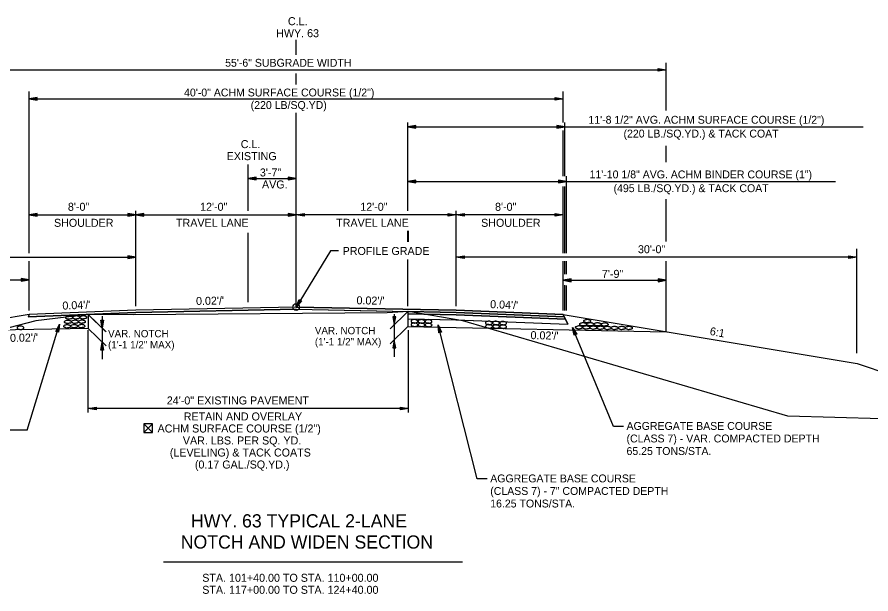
# Model space of a CAD drawing. Extents: x 1461846 to 1462006, y 1686171 to 1686805.
# Drawn here: x 1461905.3 to 1461969.2, y 1686761.5 to 1686804.7 of the extents above; entities that cross this region are included whole.
import ezdxf

# ---------------------------------------------------------------- set-up
doc = ezdxf.new("R2010")
doc.units = 0
for name, color, linetype in [('1', 7, 'Continuous'), ('10', 7, 'Continuous'), ('12', 7, 'Continuous'), ('19', 7, 'Continuous'), ('20', 7, 'Continuous'), ('3', 7, 'Continuous'), ('42', 7, 'Continuous'), ('R_Draft', 7, 'Continuous')]:
    doc.layers.add(name, color=color, linetype=linetype)

# ---------------------------------------------------------------- blocks, each defined once
blk = doc.blocks.new('ROCKS')
at = {"layer": '1'}
blk.add_spline([(0.013, 0.06), (0.053, 0.053), (0.107, 0.033), (0.133, 0.013), (0.133, -0.007), (0.12, -0.033), (0.107, -0.04), (0.073, -0.053), (0.033, -0.067), (0.013, -0.067), (-0.02, -0.06), (-0.06, -0.053), (-0.087, -0.047), (-0.113, -0.02), (-0.113, -0.007), (-0.107, 0.02), (-0.087, 0.033), (-0.067, 0.047), (-0.033, 0.053), (-0.02, 0.06), (0.013, 0.06)], degree=3, dxfattribs=at)

msp = doc.modelspace()

# ---------------------------------------------------------------- linework, layer by layer
at = {"layer": '10'}
for p, q in [((1461915.407, 1686774.246), (1461914.766, 1686773.605)), ((1461914.766, 1686774.246), (1461915.407, 1686773.605))]:
    msp.add_line(p, q, dxfattribs=at)
msp.add_lwpolyline([(1461915.158, 1686773.605), (1461915.407, 1686773.605), (1461915.407, 1686774.246), (1461914.766, 1686774.246), (1461914.766, 1686773.605), (1461915.147, 1686773.605)], dxfattribs=at)
at = {"layer": '19'}
for p, q in [((1461953.889, 1686797.714), (1461953.889, 1686801.288)), ((1461898.458, 1686800.767), (1461953.889, 1686800.767)), ((1461953.289, 1686800.662), (1461953.289, 1686800.872)), ((1461953.289, 1686800.872), (1461953.889, 1686800.767)), ((1461953.289, 1686800.817), (1461953.729, 1686800.782)), ((1461953.889, 1686800.767), (1461953.289, 1686800.662)), ((1461953.729, 1686800.752), (1461953.289, 1686800.712)), ((1461906.174, 1686790.205), (1461906.174, 1686799.138)), ((1461946.174, 1686797.714), (1461946.174, 1686799.138)), ((1461906.774, 1686798.7), (1461906.174, 1686798.595)), ((1461906.174, 1686798.595), (1461946.174, 1686798.595)), ((1461906.174, 1686798.595), (1461906.774, 1686798.49)), ((1461906.774, 1686798.645), (1461906.334, 1686798.61)), ((1461906.334, 1686798.58), (1461906.774, 1686798.54)), ((1461906.774, 1686798.49), (1461906.774, 1686798.7)), ((1461945.574, 1686798.49), (1461945.574, 1686798.7)), ((1461945.574, 1686798.7), (1461946.174, 1686798.595)), ((1461945.574, 1686798.645), (1461946.014, 1686798.61)), ((1461946.174, 1686798.595), (1461945.574, 1686798.49)), ((1461946.014, 1686798.58), (1461945.574, 1686798.54)), ((1461926.174, 1686782.995), (1461926.175, 1686797.55)), ((1461946.174, 1686796.817), (1461946.174, 1686797.714)), ((1461946.174, 1686792.8), (1461946.174, 1686796.222)), ((1461953.889, 1686793.84), (1461953.889, 1686795.083)), ((1461922.591, 1686790.2), (1461922.591, 1686793.681)), ((1461946.174, 1686791.088), (1461946.174, 1686792.022)), ((1461946.174, 1686787.026), (1461946.174, 1686791.088)), ((1461953.889, 1686787.911), (1461953.889, 1686791.088)), ((1461922.591, 1686783.353), (1461922.591, 1686788.545)), ((1461884.174, 1686786.726), (1461914.174, 1686786.726)), ((1461913.574, 1686786.832), (1461913.574, 1686786.622)), ((1461914.174, 1686786.726), (1461913.574, 1686786.832)), ((1461914.014, 1686786.741), (1461913.574, 1686786.777)), ((1461913.574, 1686786.622), (1461914.174, 1686786.726)), ((1461913.574, 1686786.672), (1461914.014, 1686786.711)), ((1461938.174, 1686786.726), (1461938.774, 1686786.832)), ((1461968.174, 1686786.726), (1461938.174, 1686786.726)), ((1461938.774, 1686786.622), (1461938.174, 1686786.726)), ((1461938.334, 1686786.741), (1461938.774, 1686786.777)), ((1461938.774, 1686786.672), (1461938.334, 1686786.711)), ((1461938.774, 1686786.832), (1461938.774, 1686786.622)), ((1461953.889, 1686781.149), (1461953.889, 1686786.44)), ((1461967.574, 1686786.621), (1461967.574, 1686786.831)), ((1461967.574, 1686786.831), (1461968.174, 1686786.726)), ((1461967.574, 1686786.776), (1461968.014, 1686786.741)), ((1461968.174, 1686786.726), (1461967.574, 1686786.621)), ((1461968.014, 1686786.711), (1461967.574, 1686786.671)), ((1461926.174, 1686782.995), (1461926.398, 1686783.562)), ((1461926.575, 1686783.452), (1461926.174, 1686782.995)), ((1461926.248, 1686783.136), (1461926.441, 1686783.53)), ((1461926.535, 1686783.474), (1461926.271, 1686783.125)), ((1461926.398, 1686783.562), (1461926.575, 1686783.452)), ((1461906.174, 1686782.435), (1461884.174, 1686778.769)), ((1461914.174, 1686782.589), (1461906.089, 1686782.265)), ((1461906.174, 1686782.435), (1461906.089, 1686782.265)), ((1461914.174, 1686782.755), (1461906.174, 1686782.435)), ((1461910.591, 1686782.445), (1461910.591, 1686781.392)), ((1461926.174, 1686782.995), (1461914.174, 1686782.755)), ((1461926.174, 1686782.829), (1461914.174, 1686782.589)), ((1461926.174, 1686782.995), (1461938.168, 1686782.755)), ((1461926.174, 1686782.829), (1461938.174, 1686782.589)), ((1461934.549, 1686782.66), (1461934.549, 1686781.535)), ((1461934.549, 1686782.494), (1461934.549, 1686782.119)), ((1461934.549, 1686782.494), (1461938.17, 1686782.422)), ((1461934.591, 1686782.494), (1461938.174, 1686782.422)), ((1461938.17, 1686782.755), (1461946.174, 1686782.435)), ((1461938.17, 1686782.589), (1461946.259, 1686782.265)), ((1461938.17, 1686782.422), (1461946.344, 1686782.095)), ((1461946.174, 1686782.435), (1461946.536, 1686781.712)), ((1461946.174, 1686782.435), (1461968.195, 1686778.765)), ((1461911.531, 1686782.022), (1461911.741, 1686782.022)), ((1461911.636, 1686781.422), (1461911.531, 1686782.022)), ((1461911.621, 1686781.582), (1461911.581, 1686782.022)), ((1461911.741, 1686782.022), (1461911.636, 1686781.422)), ((1461911.686, 1686782.022), (1461911.651, 1686781.582)), ((1461933.631, 1686782.259), (1461933.421, 1686782.259)), ((1461933.421, 1686782.259), (1461933.526, 1686781.659)), ((1461933.476, 1686782.259), (1461933.511, 1686781.819)), ((1461933.526, 1686781.659), (1461933.631, 1686782.259)), ((1461933.541, 1686781.819), (1461933.581, 1686782.259)), ((1461934.549, 1686782.119), (1461938.17, 1686782.047)), ((1461934.591, 1686782.119), (1461938.174, 1686782.047)), ((1461938.17, 1686782.047), (1461946.536, 1686781.712)), ((1461946.536, 1686781.712), (1461946.344, 1686782.095)), ((1461946.344, 1686782.095), (1461946.344, 1686782.095)), ((1461910.591, 1686781.392), (1461898.458, 1686781.149)), ((1461906.015, 1686773.763), (1461908.439, 1686781.715)), ((1461908.164, 1686781.173), (1461908.439, 1686781.715)), ((1461908.364, 1686781.111), (1461908.164, 1686781.173)), ((1461908.212, 1686781.159), (1461908.377, 1686781.567)), ((1461908.404, 1686781.559), (1461908.314, 1686781.129)), ((1461908.439, 1686781.715), (1461908.364, 1686781.111)), ((1461934.549, 1686781.536), (1461953.889, 1686781.149)), ((1461939.74, 1686770.123), (1461936.815, 1686781.67)), ((1461936.864, 1686781.064), (1461936.815, 1686781.67)), ((1461936.815, 1686781.67), (1461937.067, 1686781.115)), ((1461936.912, 1686781.077), (1461936.839, 1686781.511)), ((1461936.867, 1686781.519), (1461937.015, 1686781.105)), ((1461946.536, 1686781.712), (1461946.536, 1686781.712)), ((1461949.951, 1686774.056), (1461946.883, 1686781.471)), ((1461947.016, 1686780.878), (1461946.883, 1686781.471)), ((1461946.883, 1686781.471), (1461947.209, 1686780.956)), ((1461947.061, 1686780.897), (1461946.929, 1686781.317)), ((1461946.955, 1686781.328), (1461947.159, 1686780.939)), ((1461933.526, 1686780.534), (1461933.421, 1686779.934)), ((1461933.631, 1686779.934), (1461933.526, 1686780.534)), ((1461937.067, 1686781.115), (1461936.864, 1686781.064)), ((1461947.209, 1686780.956), (1461947.016, 1686780.878)), ((1461911.531, 1686779.769), (1461911.636, 1686780.369)), ((1461911.586, 1686779.769), (1461911.621, 1686780.209)), ((1461911.636, 1686780.369), (1461911.741, 1686779.769)), ((1461911.651, 1686780.209), (1461911.691, 1686779.769)), ((1461933.421, 1686779.934), (1461933.631, 1686779.934)), ((1461933.511, 1686780.374), (1461933.471, 1686779.934)), ((1461933.576, 1686779.934), (1461933.541, 1686780.374)), ((1461911.741, 1686779.769), (1461911.531, 1686779.769)), ((1461968.195, 1686778.765), (1461981.629, 1686774.287)), ((1461906.015, 1686773.763), (1461901.805, 1686773.763)), ((1461950.688, 1686774.056), (1461949.951, 1686774.056)), ((1461940.477, 1686770.123), (1461939.74, 1686770.123))]:
    msp.add_line(p, q, dxfattribs=at)
for points in [[(1461929.357, 1686787.194), (1461928.757, 1686787.194), (1461926.174, 1686782.995)], [(1461946.344, 1686782.095), (1461938.174, 1686782.422), (1461934.549, 1686782.494), (1461934.549, 1686782.494), (1461934.549, 1686782.494)], [(1461934.549, 1686782.119), (1461934.549, 1686782.119), (1461934.549, 1686782.119), (1461938.148, 1686782.047), (1461946.536, 1686781.712)], [(1461994.384, 1686773.924), (1461984.134, 1686774.215), (1461963.023, 1686774.822)]]:
    msp.add_lwpolyline(points, dxfattribs=at)
for points in [[(1461906.089, 1686782.265), (1461914.174, 1686782.589), (1461926.174, 1686782.829), (1461938.259, 1686782.585), (1461946.259, 1686782.265), (1461946.174, 1686782.435), (1461938.168, 1686782.755), (1461926.174, 1686782.995), (1461914.174, 1686782.755), (1461906.174, 1686782.435)], [(1461934.549, 1686782.494), (1461934.549, 1686782.494), (1461934.549, 1686782.494), (1461938.174, 1686782.422), (1461946.344, 1686782.095), (1461946.344, 1686782.095), (1461946.259, 1686782.265), (1461938.17, 1686782.589), (1461934.549, 1686782.66), (1461934.549, 1686782.66), (1461934.549, 1686782.66), (1461934.549, 1686782.66)]]:
    msp.add_lwpolyline(points, close=True, dxfattribs=at)
msp.add_circle((1461926.179, 1686782.993), 0.25, dxfattribs=at)
at = {"layer": '20'}
for p, q in [((1461934.549, 1686790.205), (1461934.549, 1686796.817)), ((1461935.149, 1686796.603), (1461934.549, 1686796.498)), ((1461934.549, 1686796.498), (1461935.149, 1686796.393)), ((1461934.549, 1686796.498), (1461946.299, 1686796.498)), ((1461935.149, 1686796.548), (1461934.709, 1686796.513)), ((1461935.149, 1686796.393), (1461935.149, 1686796.603)), ((1461945.699, 1686796.603), (1461945.699, 1686796.393)), ((1461946.299, 1686796.498), (1461945.699, 1686796.603)), ((1461946.139, 1686796.513), (1461945.699, 1686796.548)), ((1461945.699, 1686796.393), (1461946.299, 1686796.498)), ((1461946.299, 1686792.8), (1461946.299, 1686796.817)), ((1461946.299, 1686796.498), (1461968.649, 1686796.498)), ((1461934.709, 1686796.483), (1461935.149, 1686796.443)), ((1461945.699, 1686796.443), (1461946.139, 1686796.483)), ((1461923.191, 1686792.727), (1461922.591, 1686792.622)), ((1461923.191, 1686792.672), (1461922.751, 1686792.637)), ((1461923.191, 1686792.517), (1461923.191, 1686792.727)), ((1461925.574, 1686792.727), (1461925.574, 1686792.517)), ((1461926.174, 1686792.622), (1461925.574, 1686792.727)), ((1461926.014, 1686792.637), (1461925.574, 1686792.672)), ((1461946.435, 1686787.026), (1461946.435, 1686792.8)), ((1461922.591, 1686792.622), (1461926.174, 1686792.622)), ((1461922.591, 1686792.622), (1461923.191, 1686792.517)), ((1461922.751, 1686792.607), (1461923.191, 1686792.567)), ((1461925.574, 1686792.517), (1461926.174, 1686792.622)), ((1461925.574, 1686792.567), (1461926.014, 1686792.607)), ((1461935.149, 1686792.51), (1461934.549, 1686792.405)), ((1461934.549, 1686792.405), (1461946.435, 1686792.405)), ((1461934.549, 1686792.405), (1461935.149, 1686792.3)), ((1461935.149, 1686792.455), (1461934.709, 1686792.42)), ((1461934.709, 1686792.39), (1461935.149, 1686792.35)), ((1461935.149, 1686792.3), (1461935.149, 1686792.51)), ((1461945.835, 1686792.51), (1461945.835, 1686792.3)), ((1461946.435, 1686792.405), (1461945.835, 1686792.51)), ((1461946.275, 1686792.42), (1461945.835, 1686792.455)), ((1461945.835, 1686792.3), (1461946.435, 1686792.405)), ((1461945.835, 1686792.35), (1461946.275, 1686792.39)), ((1461946.299, 1686787.026), (1461946.299, 1686792.022)), ((1461946.435, 1686792.405), (1461957.904, 1686792.405)), ((1461957.904, 1686792.405), (1461966.582, 1686792.405)), ((1461906.174, 1686787.026), (1461906.174, 1686790.205)), ((1461914.174, 1686783.055), (1461914.174, 1686790.205)), ((1461938.174, 1686783.055), (1461938.174, 1686790.205)), ((1461946.174, 1686787.026), (1461946.174, 1686790.205)), ((1461906.774, 1686790.01), (1461906.174, 1686789.905)), ((1461906.174, 1686789.905), (1461914.174, 1686789.905)), ((1461906.174, 1686789.905), (1461906.774, 1686789.8)), ((1461906.774, 1686789.955), (1461906.334, 1686789.92)), ((1461906.334, 1686789.89), (1461906.774, 1686789.85)), ((1461906.774, 1686789.8), (1461906.774, 1686790.01)), ((1461913.574, 1686790.01), (1461913.574, 1686789.8)), ((1461914.174, 1686789.905), (1461913.574, 1686790.01)), ((1461914.014, 1686789.92), (1461913.574, 1686789.955)), ((1461913.574, 1686789.8), (1461914.174, 1686789.905)), ((1461913.574, 1686789.85), (1461914.014, 1686789.89)), ((1461914.774, 1686790.01), (1461914.174, 1686789.905)), ((1461914.174, 1686789.905), (1461926.174, 1686789.905)), ((1461914.174, 1686789.905), (1461914.774, 1686789.8)), ((1461914.774, 1686789.955), (1461914.334, 1686789.92)), ((1461914.334, 1686789.89), (1461914.774, 1686789.85)), ((1461914.774, 1686789.8), (1461914.774, 1686790.01)), ((1461925.574, 1686790.01), (1461925.574, 1686789.8)), ((1461926.174, 1686789.905), (1461925.574, 1686790.01)), ((1461926.014, 1686789.92), (1461925.574, 1686789.955)), ((1461925.574, 1686789.8), (1461926.174, 1686789.905)), ((1461925.574, 1686789.85), (1461926.014, 1686789.89)), ((1461926.174, 1686789.905), (1461926.774, 1686790.01)), ((1461938.174, 1686789.905), (1461926.174, 1686789.905)), ((1461926.774, 1686789.8), (1461926.174, 1686789.905)), ((1461926.334, 1686789.92), (1461926.774, 1686789.955)), ((1461926.774, 1686789.85), (1461926.334, 1686789.89)), ((1461926.774, 1686790.01), (1461926.774, 1686789.8)), ((1461937.574, 1686789.8), (1461937.574, 1686790.01)), ((1461937.574, 1686790.01), (1461938.174, 1686789.905)), ((1461937.574, 1686789.955), (1461938.014, 1686789.92)), ((1461938.174, 1686789.905), (1461937.574, 1686789.8)), ((1461938.014, 1686789.89), (1461937.574, 1686789.85)), ((1461938.174, 1686789.905), (1461938.774, 1686790.01)), ((1461946.174, 1686789.905), (1461938.174, 1686789.905)), ((1461938.774, 1686789.8), (1461938.174, 1686789.905)), ((1461938.334, 1686789.92), (1461938.774, 1686789.955)), ((1461938.774, 1686789.85), (1461938.334, 1686789.89)), ((1461938.774, 1686790.01), (1461938.774, 1686789.8)), ((1461945.574, 1686789.8), (1461945.574, 1686790.01)), ((1461945.574, 1686790.01), (1461946.174, 1686789.905)), ((1461945.574, 1686789.955), (1461946.014, 1686789.92)), ((1461946.174, 1686789.905), (1461945.574, 1686789.8)), ((1461946.014, 1686789.89), (1461945.574, 1686789.85)), ((1461934.549, 1686787.885), (1461934.549, 1686788.692)), ((1461934.591, 1686787.885), (1461934.591, 1686788.692)), ((1461968.174, 1686779.551), (1461968.174, 1686787.36)), ((1461906.174, 1686782.735), (1461906.174, 1686786.426)), ((1461934.549, 1686783.055), (1461934.549, 1686786.564)), ((1461946.174, 1686782.735), (1461946.174, 1686786.426)), ((1461946.299, 1686785.46), (1461946.299, 1686786.426)), ((1461946.435, 1686785.46), (1461946.435, 1686786.426)), ((1461898.458, 1686785.032), (1461906.174, 1686785.032)), ((1461905.574, 1686785.137), (1461905.574, 1686784.927)), ((1461906.174, 1686785.032), (1461905.574, 1686785.137)), ((1461906.014, 1686785.047), (1461905.574, 1686785.082)), ((1461905.574, 1686784.927), (1461906.174, 1686785.032)), ((1461905.574, 1686784.977), (1461906.014, 1686785.017)), ((1461946.774, 1686785.102), (1461946.174, 1686784.997)), ((1461946.174, 1686784.997), (1461953.889, 1686784.997)), ((1461946.174, 1686784.997), (1461946.774, 1686784.892)), ((1461946.774, 1686785.047), (1461946.334, 1686785.012)), ((1461946.334, 1686784.982), (1461946.774, 1686784.942)), ((1461946.774, 1686784.892), (1461946.774, 1686785.102)), ((1461953.289, 1686785.102), (1461953.289, 1686784.892)), ((1461953.889, 1686784.997), (1461953.289, 1686785.102)), ((1461953.729, 1686785.012), (1461953.289, 1686785.047)), ((1461953.289, 1686784.892), (1461953.889, 1686784.997)), ((1461953.289, 1686784.942), (1461953.729, 1686784.982)), ((1461946.299, 1686782.735), (1461946.299, 1686784.622)), ((1461946.435, 1686782.735), (1461946.435, 1686784.603)), ((1461910.591, 1686782.445), (1461911.874, 1686781.189)), ((1461910.591, 1686782.445), (1461911.935, 1686781.13)), ((1461934.549, 1686782.661), (1461933.227, 1686781.367)), ((1461910.591, 1686781.392), (1461911.935, 1686780.076)), ((1461910.591, 1686775.096), (1461910.591, 1686781.268)), ((1461934.549, 1686781.536), (1461933.227, 1686780.242)), ((1461934.591, 1686775.096), (1461934.591, 1686781.268)), ((1461910.591, 1686775.396), (1461911.191, 1686775.501)), ((1461934.591, 1686775.396), (1461910.591, 1686775.396)), ((1461911.191, 1686775.291), (1461910.591, 1686775.396)), ((1461910.751, 1686775.411), (1461911.191, 1686775.446)), ((1461911.191, 1686775.341), (1461910.751, 1686775.381)), ((1461911.191, 1686775.501), (1461911.191, 1686775.291)), ((1461933.991, 1686775.291), (1461933.991, 1686775.501)), ((1461933.991, 1686775.501), (1461934.591, 1686775.396)), ((1461933.991, 1686775.446), (1461934.431, 1686775.411)), ((1461934.591, 1686775.396), (1461933.991, 1686775.291)), ((1461934.431, 1686775.381), (1461933.991, 1686775.341))]:
    msp.add_line(p, q, dxfattribs=at)
for points in [[(1461933.526, 1686782.451), (1461933.526, 1686779.253)], [(1461911.636, 1686782.299), (1461911.636, 1686779.089)]]:
    msp.add_lwpolyline(points, dxfattribs=at)
at = {"layer": '3'}
msp.add_line((1461916.225, 1686763.91), (1461938.65, 1686763.91), dxfattribs=at)
at = {"layer": 'R_Draft'}
for p, q in [((1461926.174, 1686801.882), (1461926.174, 1686803.026)), ((1461926.174, 1686799.663), (1461926.174, 1686800.494))]:
    msp.add_line(p, q, dxfattribs=at)
msp.add_lwpolyline([(1461963.023, 1686774.822), (1461938.674, 1686781.973), (1461934.591, 1686782.66), (1461933.001, 1686782.563), (1461913.998, 1686782.421), (1461910.591, 1686782.445), (1461906.674, 1686781.973), (1461896.057, 1686779.215), (1461891.841, 1686777.956), (1461883.145, 1686780.632), (1461874.28, 1686780.674), (1461858.704, 1686780.674)], dxfattribs=at)

# ---------------------------------------------------------------- block references
at = {"layer": '19'}
for p, xscale, yscale, rotation in [((1461909.089, 1686781.893), 2.061136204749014, -2.061136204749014, -179.20800457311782), ((1461909.178, 1686782.217), 2.061136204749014, -2.061136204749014, -179.20800457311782), ((1461909.62, 1686781.901), 2.061136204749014, -2.061136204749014, -179.20800457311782), ((1461909.709, 1686782.225), 2.061136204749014, -2.061136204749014, -179.20800457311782), ((1461910.142, 1686781.908), 2.061136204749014, -2.061136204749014, -179.20800457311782), ((1461910.243, 1686782.232), 2.061136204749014, -2.061136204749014, -179.20800457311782), ((1461935.016, 1686781.936), 2.0611362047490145, 2.0611362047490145, -2.9543097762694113), ((1461935.019, 1686781.674), 2.0611362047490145, 2.0611362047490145, -2.9543097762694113), ((1461935.545, 1686781.928), 2.0611362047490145, 2.0611362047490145, -2.9543097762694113), ((1461935.548, 1686781.666), 2.0611362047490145, 2.0611362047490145, -2.9543097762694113), ((1461936.075, 1686781.92), 2.0611362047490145, 2.0611362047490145, -2.9543097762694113), ((1461936.078, 1686781.658), 2.0611362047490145, 2.0611362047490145, -2.9543097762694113), ((1461940.601, 1686781.81), 2.0611362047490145, 2.0611362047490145, -2.9543097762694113), ((1461941.13, 1686781.802), 2.0611362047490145, 2.0611362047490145, -2.9543097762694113), ((1461941.659, 1686781.794), 2.0611362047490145, 2.0611362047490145, -2.9543097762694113), ((1461947.691, 1686781.714), 2.061136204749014, -2.061136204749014, 180), ((1461947.996, 1686781.952), 2.061136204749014, -2.061136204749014, 180), ((1461948.233, 1686781.714), 2.061136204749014, -2.061136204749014, 180), ((1461948.767, 1686781.714), 2.061136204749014, -2.061136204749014, 180), ((1461949.309, 1686781.698), 2.061136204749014, -2.061136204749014, 180), ((1461909.04, 1686781.561), 2.061136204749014, -2.061136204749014, -179.20800457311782), ((1461909.57, 1686781.569), 2.061136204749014, -2.061136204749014, -179.20800457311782), ((1461910.104, 1686781.576), 2.061136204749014, -2.061136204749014, -179.20800457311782), ((1461940.604, 1686781.549), 2.0611362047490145, 2.0611362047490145, -2.9543097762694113), ((1461941.133, 1686781.54), 2.0611362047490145, 2.0611362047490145, -2.9543097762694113), ((1461941.663, 1686781.532), 2.0611362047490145, 2.0611362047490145, -2.9543097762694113), ((1461947.383, 1686781.48), 2.061136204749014, -2.061136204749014, 180), ((1461947.928, 1686781.471), 2.061136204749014, -2.061136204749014, 180), ((1461948.461, 1686781.461), 2.061136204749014, -2.061136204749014, 180), ((1461948.986, 1686781.449), 2.061136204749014, -2.061136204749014, 180), ((1461949.517, 1686781.434), 2.061136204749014, -2.061136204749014, 180), ((1461950.044, 1686781.434), 2.061136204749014, -2.061136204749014, 180), ((1461950.587, 1686781.434), 2.061136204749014, -2.061136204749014, 180), ((1461951.126, 1686781.434), 2.061136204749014, -2.061136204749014, 180)]:
    msp.add_blockref('ROCKS', p, dxfattribs=dict(at, xscale=xscale, yscale=yscale, rotation=rotation))
at = {"layer": '19', "xscale": 2.061136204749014, "yscale": 2.061136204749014}
msp.add_blockref('ROCKS', (1461905.505, 1686781.447), dxfattribs=at)

# ---------------------------------------------------------------- texts
at = {"layer": '10'}
for s, p in [('VAR. NOTCH', (1461912.085, 1686780.726)), ('VAR. NOTCH', (1461927.578, 1686780.955)), ('(1\'-1 1/2" MAX)', (1461927.578, 1686780.126)), ('(1\'-1 1/2" MAX)', (1461912.085, 1686779.897))]:
    msp.add_text(s, height=0.55, dxfattribs=at).set_placement(p)
for s, p in [('STA. 101+40.00 TO STA. 110+00.00', (1461919.14, 1686762.41)), ('STA. 117+00.00 TO STA. 124+40.00', (1461919.14, 1686761.51))]:
    msp.add_text(s, height=0.6, rotation=359.99538, dxfattribs=at).set_placement(p)
at = {"layer": '12'}
for s, p in [('HWY. 63 TYPICAL 2-LANE ', (1461918.298, 1686766.482)), ('NOTCH AND WIDEN SECTION', (1461917.53, 1686764.898))]:
    msp.add_text(s, height=0.98999, rotation=359.99538, dxfattribs=at).set_placement(p)
at = {"layer": '19'}
for s, p in [('55\'-6" SUBGRADE WIDTH', (1461920.855, 1686800.998)), ('40\'-0" ACHM SURFACE COURSE (1/2")', (1461917.779, 1686798.773)), ('(220 LB/SQ.YD)', (1461922.769, 1686797.833))]:
    msp.add_text(s, height=0.59001, dxfattribs=at).set_placement(p)
for s, p in [('AGGREGATE BASE COURSE', (1461950.927, 1686773.791)), ('(CLASS 7) - VAR. COMPACTED DEPTH', (1461950.927, 1686772.851)), ('65.25 TONS/STA.', (1461950.927, 1686771.911)), ('AGGREGATE BASE COURSE', (1461940.716, 1686769.858)), ('(CLASS 7) - 7" COMPACTED DEPTH', (1461940.716, 1686768.918)), ('16.25 TONS/STA.', (1461940.716, 1686767.978))]:
    msp.add_text(s, height=0.59001, rotation=360, dxfattribs=at).set_placement(p)
at = {"layer": '42'}
for s, p in [('11\'-8 1/2" AVG. ACHM SURFACE COURSE (1/2")', (1461948.071, 1686796.729)), ('(220 LB./SQ.YD.) & TACK COAT', (1461950.702, 1686795.696)), ('11\'-10 1/8" AVG. ACHM BINDER COURSE (1")', (1461948.156, 1686792.636)), ('(495 LB./SQ.YD.) & TACK COAT', (1461949.956, 1686791.603))]:
    msp.add_text(s, height=0.59001, rotation=360, dxfattribs=at).set_placement(p)
at = {"layer": 'R_Draft'}
for s, rotation, p in [('C.L.', 360, (1461925.558, 1686804.11)), ('HWY. 63', 360, (1461924.679, 1686803.21)), ('C.L.', 360, (1461922.026, 1686794.9)), ('EXISTING', 360, (1461920.97, 1686794)), ('3\'-7"', 360, (1461923.458, 1686792.778)), ('AVG.', 360, (1461923.616, 1686791.878)), ('8\'-0"', 360, (1461909.076, 1686790.205)), ('12\'-0"', 360, (1461918.977, 1686790.205)), ('SHOULDER', 360, (1461908.032, 1686789.005)), ('TRAVEL LANE', 360, (1461917.174, 1686789.005)), ('PROFILE GRADE', 360, (1461929.657, 1686786.894)), ('7\'-9"', 360, (1461949.084, 1686785.18)), ("0.02'/'", 1.14576, (1461918.68, 1686783.145)), ("0.02'/'", 358.85424, (1461930.692, 1686783.205)), ("0.04'/'", 2.29061, (1461908.675, 1686782.796)), ("0.04'/'", 357.70939, (1461940.699, 1686782.915)), ("0.02'/'", 358.85424, (1461943.731, 1686780.59)), ('6:1', 349.3289, (1461957.131, 1686780.915)), ("0.02'/'", 1.14576, (1461904.742, 1686780.38))]:
    msp.add_text(s, height=0.6, rotation=rotation, dxfattribs=at).set_placement(p)
for s, p in [('12\'-0"', (1461930.977, 1686790.205)), ('8\'-0"', (1461941.076, 1686790.205)), ('TRAVEL LANE', (1461929.174, 1686789.005)), ('SHOULDER', (1461940.032, 1686789.005)), ('30\'-0"', (1461951.783, 1686787.026)), ('24\'-0" EXISTING PAVEMENT', (1461916.485, 1686775.696)), ('RETAIN AND OVERLAY', (1461917.753, 1686774.496)), ('ACHM SURFACE COURSE (1/2")', (1461915.792, 1686773.596)), ('VAR. LBS. PER SQ. YD.', (1461917.687, 1686772.696)), ('(LEVELING) & TACK COATS', (1461916.709, 1686771.796)), ('(0.17 GAL./SQ.YD.)', (1461918.589, 1686770.896))]:
    msp.add_text(s, height=0.6, dxfattribs=at).set_placement(p)

doc.saveas('drawing.dxf')
